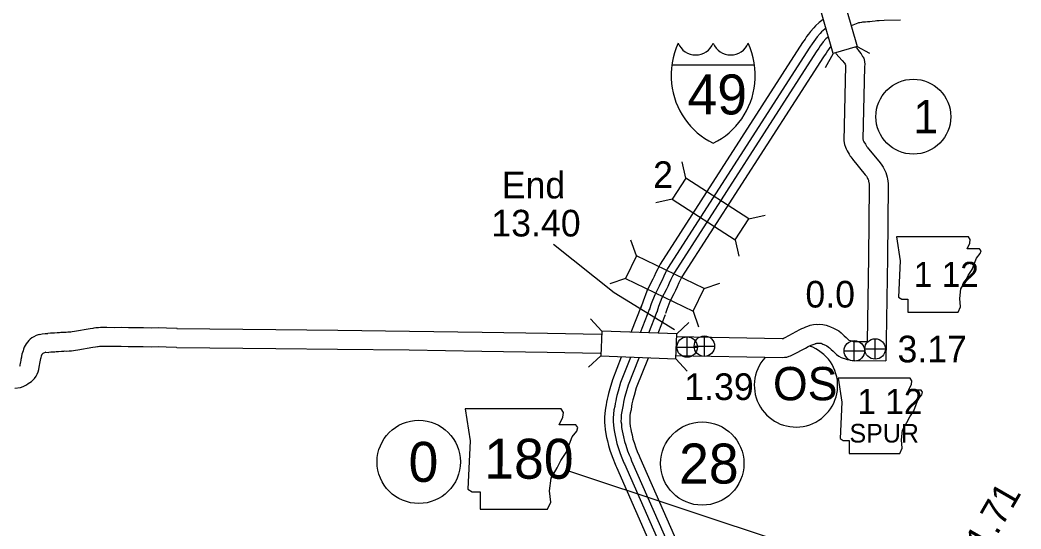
# Model space of a CAD drawing. Extents: x -939622 to -934245, y 1383184 to 1385301.
# Drawn here: x -936375.77 to -936328.22, y 1384954.58 to 1384978.78 of the extents above; entities that cross this region are included whole.
import ezdxf

# ---------------------------------------------------------------- set-up
doc = ezdxf.new("R2010")
doc.units = 0
for name, color, linetype in [('10', 7, 'Continuous'), ('19', 7, 'Continuous'), ('20', 7, 'Continuous'), ('21', 7, 'Continuous'), ('22', 7, 'Continuous'), ('23', 7, 'Continuous'), ('25', 7, 'Continuous'), ('26', 7, 'Continuous'), ('27', 7, 'Continuous')]:
    doc.layers.add(name, color=color, linetype=linetype)

msp = doc.modelspace()

# ---------------------------------------------------------------- linework, layer by layer
at = {"layer": '10'}
for points in [[(-936336.07, 1384977.478), (-936336.03, 1384977.434), (-936335.906, 1384977.282), (-936335.82, 1384977.17), (-936335.746, 1384977.033), (-936335.739, 1384977.02), (-936335.697, 1384976.953), (-936335.653, 1384976.803), (-936335.644, 1384976.662), (-936335.656, 1384976.563), (-936335.657, 1384976.552), (-936335.731, 1384973.105), (-936335.725, 1384973.072), (-936335.72, 1384973.054), (-936335.699, 1384973.01), (-936335.686, 1384972.977), (-936335.617, 1384972.876), (-936335.54, 1384972.746)], [(-936337.024, 1384977.185), (-936336.711, 1384976.845), (-936336.611, 1384976.723), (-936336.578, 1384976.679), (-936336.554, 1384976.634), (-936336.557, 1384976.596), (-936336.632, 1384973.033), (-936336.602, 1384972.863), (-936336.564, 1384972.737), (-936336.524, 1384972.649), (-936336.483, 1384972.55), (-936336.429, 1384972.47), (-936336.386, 1384972.396), (-936336.339, 1384972.31), (-936336.306, 1384972.273), (-936336.266, 1384972.207), (-936336.209, 1384972.144)], [(-936335.526, 1384972.73), (-936334.92, 1384971.982), (-936334.833, 1384971.874), (-936334.773, 1384971.778), (-936334.722, 1384971.686), (-936334.69, 1384971.614), (-936334.648, 1384971.52), (-936334.612, 1384971.414), (-936334.585, 1384971.31), (-936334.567, 1384971.206), (-936334.552, 1384971.133), (-936334.539, 1384970.99), (-936334.534, 1384970.89), (-936334.565, 1384967.491), (-936334.651, 1384962.577)], [(-936336.225, 1384972.163), (-936335.621, 1384971.417), (-936335.569, 1384971.352), (-936335.55, 1384971.322), (-936335.528, 1384971.283), (-936335.512, 1384971.247), (-936335.487, 1384971.192), (-936335.474, 1384971.154), (-936335.465, 1384971.12), (-936335.452, 1384971.037), (-936335.443, 1384970.997), (-936335.437, 1384970.93), (-936335.434, 1384970.874), (-936335.465, 1384967.503), (-936335.535, 1384963.488)], [(-936368.307, 1384964.112), (-936368.812, 1384964.129), (-936369.206, 1384964.134), (-936369.534, 1384964.129), (-936369.904, 1384964.14), (-936370.259, 1384964.141), (-936370.618, 1384964.14), (-936370.959, 1384964.151), (-936371.306, 1384964.149), (-936371.651, 1384964.16), (-936371.844, 1384964.159), (-936371.943, 1384964.152), (-936372.049, 1384964.149), (-936372.169, 1384964.14), (-936372.262, 1384964.123), (-936372.322, 1384964.111), (-936372.439, 1384964.099), (-936373.185, 1384963.97), (-936373.303, 1384963.947), (-936373.364, 1384963.935), (-936373.378, 1384963.934), (-936373.453, 1384963.933), (-936373.471, 1384963.93), (-936373.507, 1384963.931), (-936373.587, 1384963.923), (-936373.643, 1384963.927), (-936373.754, 1384963.923), (-936373.842, 1384963.918), (-936373.902, 1384963.909), (-936374.012, 1384963.903), (-936374.128, 1384963.893), (-936374.203, 1384963.887), (-936374.247, 1384963.882), (-936374.331, 1384963.882), (-936374.451, 1384963.875)], [(-936368.318, 1384964.112), (-936363.619, 1384964.061), (-936360.681, 1384964.028), (-936357.272, 1384963.988), (-936353.815, 1384963.939), (-936350.716, 1384963.886), (-936348.171, 1384963.834)], [(-936344.611, 1384963.724), (-936339.574, 1384963.634), (-936339.523, 1384963.638), (-936339.516, 1384963.64), (-936339.476, 1384963.664), (-936339.433, 1384963.682), (-936338.902, 1384963.964), (-936338.735, 1384964.065), (-936338.631, 1384964.106), (-936338.534, 1384964.144), (-936338.442, 1384964.183), (-936338.349, 1384964.219), (-936338.235, 1384964.268), (-936338.083, 1384964.294), (-936337.959, 1384964.309), (-936337.867, 1384964.306), (-936337.795, 1384964.309), (-936337.635, 1384964.305), (-936337.473, 1384964.272), (-936337.355, 1384964.228), (-936337.266, 1384964.191), (-936337.123, 1384964.124), (-936337.036, 1384964.082), (-936336.885, 1384963.999), (-936336.766, 1384963.907), (-936336.687, 1384963.829), (-936336.618, 1384963.763), (-936336.528, 1384963.674), (-936336.465, 1384963.614), (-936336.423, 1384963.574), (-936336.405, 1384963.562), (-936336.331, 1384963.541), (-936336.288, 1384963.526), (-936336.262, 1384963.518), (-936336.223, 1384963.505), (-936336.207, 1384963.501), (-936336.197, 1384963.499), (-936336.092, 1384963.495), (-936335.535, 1384963.488)], [(-936374.855, 1384963.823), (-936374.912, 1384963.801), (-936374.999, 1384963.773), (-936375.115, 1384963.717), (-936375.205, 1384963.662), (-936375.289, 1384963.603), (-936375.355, 1384963.537), (-936375.419, 1384963.464), (-936375.479, 1384963.384), (-936375.532, 1384963.299), (-936375.573, 1384963.224), (-936375.604, 1384963.131), (-936375.623, 1384963.033)], [(-936374.855, 1384963.823), (-936374.723, 1384963.854), (-936374.586, 1384963.866), (-936374.451, 1384963.875)], [(-936375.781, 1384962.317), (-936375.769, 1384962.349), (-936375.76, 1384962.377), (-936375.748, 1384962.44), (-936375.731, 1384962.529), (-936375.719, 1384962.581), (-936375.714, 1384962.656), (-936375.689, 1384962.769), (-936375.667, 1384962.9), (-936375.636, 1384962.992), (-936375.622, 1384963.04), (-936375.621, 1384963.045)], [(-936374.543, 1384962.978), (-936374.618, 1384962.951), (-936374.663, 1384962.936), (-936374.684, 1384962.926), (-936374.705, 1384962.913), (-936374.72, 1384962.896), (-936374.737, 1384962.873), (-936374.737, 1384962.873), (-936374.739, 1384962.861)], [(-936374.543, 1384962.978), (-936374.397, 1384962.976)], [(-936368.338, 1384963.212), (-936368.833, 1384963.229), (-936369.205, 1384963.234), (-936369.541, 1384963.229), (-936369.919, 1384963.24), (-936370.259, 1384963.241), (-936370.63, 1384963.24), (-936370.971, 1384963.251), (-936371.319, 1384963.249), (-936371.663, 1384963.26), (-936371.811, 1384963.259), (-936371.897, 1384963.253), (-936372.001, 1384963.25), (-936372.054, 1384963.246), (-936372.093, 1384963.239), (-936372.189, 1384963.22), (-936372.316, 1384963.207), (-936373.024, 1384963.084), (-936373.133, 1384963.064), (-936373.228, 1384963.045), (-936373.327, 1384963.034), (-936373.439, 1384963.034), (-936373.574, 1384963.019), (-936373.661, 1384963.026), (-936373.712, 1384963.024), (-936373.75, 1384963.022), (-936373.809, 1384963.013), (-936373.95, 1384963.005), (-936374.05, 1384962.997), (-936374.119, 1384962.991), (-936374.2, 1384962.982), (-936374.302, 1384962.982), (-936374.397, 1384962.976)], [(-936368.328, 1384963.212), (-936363.629, 1384963.161), (-936360.691, 1384963.128), (-936357.283, 1384963.088), (-936353.829, 1384963.039), (-936350.733, 1384962.986), (-936348.208, 1384962.934)], [(-936344.657, 1384962.825), (-936339.545, 1384962.733), (-936339.462, 1384962.74), (-936339.344, 1384962.741), (-936339.231, 1384962.787), (-936339.179, 1384962.805), (-936339.111, 1384962.835), (-936339.074, 1384962.857), (-936339.046, 1384962.869), (-936338.459, 1384963.18), (-936338.334, 1384963.255), (-936338.301, 1384963.269), (-936338.194, 1384963.31), (-936338.101, 1384963.35), (-936338.009, 1384963.386), (-936337.98, 1384963.398), (-936337.952, 1384963.403), (-936337.92, 1384963.407), (-936337.862, 1384963.405), (-936337.785, 1384963.408), (-936337.735, 1384963.407), (-936337.723, 1384963.405), (-936337.686, 1384963.391), (-936337.63, 1384963.368), (-936337.508, 1384963.31), (-936337.446, 1384963.281), (-936337.381, 1384963.245), (-936337.361, 1384963.23), (-936337.314, 1384963.183), (-936337.245, 1384963.117), (-936337.154, 1384963.027), (-936337.084, 1384962.961), (-936336.988, 1384962.87), (-936336.874, 1384962.793), (-936336.765, 1384962.733), (-936336.673, 1384962.703), (-936336.605, 1384962.683), (-936336.565, 1384962.669), (-936336.53, 1384962.659), (-936336.48, 1384962.642), (-936336.43, 1384962.629), (-936336.32, 1384962.602), (-936336.113, 1384962.595), (-936334.651, 1384962.577)], [(-936376.016, 1384961.267), (-936375.748, 1384961.302), (-936375.631, 1384961.358), (-936375.564, 1384961.388), (-936375.498, 1384961.417), (-936375.397, 1384961.477), (-936375.333, 1384961.52), (-936375.3, 1384961.545), (-936375.234, 1384961.584), (-936375.141, 1384961.678), (-936375.085, 1384961.74), (-936375.011, 1384961.847), (-936374.959, 1384961.946), (-936374.918, 1384962.052), (-936374.886, 1384962.156), (-936374.863, 1384962.274), (-936374.85, 1384962.346), (-936374.827, 1384962.445), (-936374.821, 1384962.526), (-936374.805, 1384962.598), (-936374.792, 1384962.679), (-936374.776, 1384962.725), (-936374.754, 1384962.802), (-936374.751, 1384962.813)], [(-936374.751, 1384962.813), (-936374.739, 1384962.861)]]:
    msp.add_lwpolyline(points, dxfattribs=at)
at = {"layer": '19'}
for points in [[(-936337.616, 1384978.802), (-936337.804, 1384978.655), (-936337.979, 1384978.504), (-936338.072, 1384978.406), (-936338.224, 1384978.235), (-936338.32, 1384978.109), (-936338.413, 1384977.988), (-936338.484, 1384977.869), (-936338.6, 1384977.711), (-936345.369, 1384967.172), (-936345.482, 1384966.954), (-936345.574, 1384966.77), (-936345.653, 1384966.576), (-936345.712, 1384966.453), (-936345.787, 1384966.306), (-936346, 1384965.88), (-936346.179, 1384965.414), (-936346.269, 1384965.137), (-936346.28, 1384965.085)], [(-936333.943, 1384978.775), (-936334.72, 1384978.753), (-936334.954, 1384978.74), (-936335.066, 1384978.732), (-936335.151, 1384978.718), (-936335.301, 1384978.703), (-936335.411, 1384978.696), (-936335.518, 1384978.687), (-936335.605, 1384978.68), (-936335.692, 1384978.676), (-936335.747, 1384978.672), (-936335.802, 1384978.663), (-936335.881, 1384978.641), (-936335.935, 1384978.635), (-936335.976, 1384978.624)], [(-936337.482, 1384978.383), (-936337.543, 1384978.336), (-936337.694, 1384978.206), (-936337.768, 1384978.127), (-936337.905, 1384977.972), (-936337.993, 1384977.858), (-936338.071, 1384977.756), (-936338.14, 1384977.641), (-936338.26, 1384977.477), (-936345.012, 1384966.965), (-936345.114, 1384966.767), (-936345.198, 1384966.6), (-936345.275, 1384966.409), (-936345.343, 1384966.269), (-936345.419, 1384966.12), (-936345.622, 1384965.714), (-936345.79, 1384965.277), (-936345.871, 1384965.027), (-936345.878, 1384964.993)], [(-936335.976, 1384978.624), (-936336.284, 1384978.504)], [(-936337.37, 1384977.99), (-936337.434, 1384977.934), (-936337.491, 1384977.874), (-936337.616, 1384977.733), (-936337.695, 1384977.63), (-936337.76, 1384977.546), (-936337.827, 1384977.433), (-936337.951, 1384977.265), (-936344.686, 1384966.777), (-936344.78, 1384966.597), (-936344.856, 1384966.445), (-936344.932, 1384966.257), (-936345.007, 1384966.102), (-936345.085, 1384965.95), (-936345.279, 1384965.562), (-936345.436, 1384965.152), (-936345.509, 1384964.927), (-936345.513, 1384964.909)], [(-936337.246, 1384977.529), (-936337.298, 1384977.471), (-936337.368, 1384977.379), (-936337.418, 1384977.314), (-936337.483, 1384977.204), (-936337.611, 1384977.031), (-936344.329, 1384966.571), (-936344.412, 1384966.41), (-936344.48, 1384966.275), (-936344.555, 1384966.09), (-936344.638, 1384965.918), (-936344.717, 1384965.764), (-936344.901, 1384965.396), (-936345.047, 1384965.015), (-936345.111, 1384964.817), (-936345.111, 1384964.815)], [(-936346.248, 1384965.197), (-936346.753, 1384963.915)], [(-936345.864, 1384965.045), (-936346.316, 1384963.897)], [(-936345.515, 1384964.908), (-936345.918, 1384963.884)], [(-936345.131, 1384964.757), (-936345.479, 1384963.874)], [(-936347.215, 1384962.74), (-936347.635, 1384961.672), (-936347.76, 1384961.247), (-936347.819, 1384961.023), (-936347.857, 1384960.872), (-936347.883, 1384960.749), (-936347.906, 1384960.606), (-936347.926, 1384960.48), (-936347.965, 1384960.321), (-936347.999, 1384960.083), (-936348.009, 1384959.875), (-936348.015, 1384959.645), (-936347.992, 1384959.492), (-936347.979, 1384959.307), (-936347.944, 1384959.102), (-936347.908, 1384958.927), (-936347.867, 1384958.777), (-936347.816, 1384958.54), (-936347.749, 1384958.331), (-936347.65, 1384958.018), (-936347.469, 1384957.574)], [(-936346.775, 1384962.732), (-936347.245, 1384961.538), (-936347.363, 1384961.137), (-936347.419, 1384960.92), (-936347.455, 1384960.778), (-936347.478, 1384960.674), (-936347.499, 1384960.542), (-936347.521, 1384960.399), (-936347.559, 1384960.242), (-936347.588, 1384960.044), (-936347.596, 1384959.86), (-936347.602, 1384959.67), (-936347.582, 1384959.538), (-936347.569, 1384959.356), (-936347.539, 1384959.179), (-936347.506, 1384959.023), (-936347.467, 1384958.875), (-936347.417, 1384958.647), (-936347.356, 1384958.456), (-936347.262, 1384958.16), (-936347.181, 1384957.965), (-936347.088, 1384957.73)], [(-936346.382, 1384962.707), (-936346.89, 1384961.416), (-936347.001, 1384961.037), (-936347.056, 1384960.827), (-936347.09, 1384960.692), (-936347.109, 1384960.605), (-936347.128, 1384960.484), (-936347.153, 1384960.326), (-936347.191, 1384960.171), (-936347.214, 1384960.009), (-936347.222, 1384959.845), (-936347.226, 1384959.693), (-936347.209, 1384959.579), (-936347.196, 1384959.401), (-936347.17, 1384959.248), (-936347.142, 1384959.11), (-936347.102, 1384958.964), (-936347.054, 1384958.743), (-936346.999, 1384958.569), (-936346.91, 1384958.289), (-936346.834, 1384958.107), (-936346.781, 1384957.974)], [(-936345.941, 1384962.701), (-936346.499, 1384961.283), (-936346.604, 1384960.926), (-936346.657, 1384960.723), (-936346.688, 1384960.599), (-936346.703, 1384960.529), (-936346.721, 1384960.419), (-936346.748, 1384960.246), (-936346.785, 1384960.092), (-936346.803, 1384959.97), (-936346.809, 1384959.83), (-936346.813, 1384959.718), (-936346.799, 1384959.625), (-936346.786, 1384959.45), (-936346.765, 1384959.325), (-936346.74, 1384959.207), (-936346.701, 1384959.062), (-936346.655, 1384958.85), (-936346.606, 1384958.694), (-936346.522, 1384958.432), (-936346.452, 1384958.263), (-936346.368, 1384958.053)], [(-936347.088, 1384957.73), (-936347.065, 1384957.673), (-936343.733, 1384950.096), (-936343.233, 1384948.977), (-936342.758, 1384947.86), (-936342.573, 1384947.412), (-936342.485, 1384947.217), (-936342.425, 1384947.071), (-936342.368, 1384946.894), (-936342.316, 1384946.757), (-936342.27, 1384946.624), (-936342.216, 1384946.438), (-936342.151, 1384946.228), (-936342.118, 1384946.053), (-936342.059, 1384945.847), (-936342.014, 1384945.642), (-936341.968, 1384945.439), (-936341.929, 1384945.276), (-936341.454, 1384942.565), (-936341.414, 1384942.38)], [(-936346.781, 1384957.974), (-936346.719, 1384957.818), (-936343.39, 1384950.247), (-936342.89, 1384949.127), (-936342.413, 1384948.005), (-936342.229, 1384947.561), (-936342.14, 1384947.366), (-936342.073, 1384947.2), (-936342.014, 1384947.018), (-936341.963, 1384946.885), (-936341.912, 1384946.737), (-936341.856, 1384946.545), (-936341.787, 1384946.318), (-936341.753, 1384946.14), (-936341.695, 1384945.938), (-936341.648, 1384945.724), (-936341.603, 1384945.524), (-936341.562, 1384945.352), (-936341.086, 1384942.637), (-936341.051, 1384942.473)], [(-936346.368, 1384958.053), (-936346.338, 1384957.977), (-936343.013, 1384950.415), (-936342.511, 1384949.292), (-936342.032, 1384948.164), (-936341.85, 1384947.724), (-936341.761, 1384947.529), (-936341.685, 1384947.342), (-936341.625, 1384947.155), (-936341.576, 1384947.027), (-936341.519, 1384946.862), (-936341.461, 1384946.663), (-936341.386, 1384946.418), (-936341.351, 1384946.235), (-936341.295, 1384946.039), (-936341.246, 1384945.814), (-936341.201, 1384945.618), (-936341.158, 1384945.435), (-936340.681, 1384942.716), (-936340.672, 1384942.676)], [(-936347.469, 1384957.574), (-936347.446, 1384957.514), (-936344.11, 1384949.928), (-936343.612, 1384948.812), (-936343.139, 1384947.7), (-936342.951, 1384947.248), (-936342.864, 1384947.054), (-936342.813, 1384946.93), (-936342.757, 1384946.757), (-936342.703, 1384946.616), (-936342.663, 1384946.499), (-936342.611, 1384946.32), (-936342.552, 1384946.128), (-936342.52, 1384945.957), (-936342.459, 1384945.746), (-936342.417, 1384945.551), (-936342.37, 1384945.346), (-936342.333, 1384945.193), (-936341.859, 1384942.486), (-936341.825, 1384942.327)]]:
    msp.add_lwpolyline(points, dxfattribs=at)
at = {"layer": '20'}
for p, q in [((-936336.001, 1384977.518), (-936335.428, 1384977.201)), ((-936337.143, 1384977.19), (-936337.527, 1384976.497)), ((-936344.151, 1384971.256), (-936344.32, 1384972.029)), ((-936344.793, 1384970.256), (-936345.567, 1384970.087)), ((-936341.152, 1384969.33), (-936340.378, 1384969.498)), ((-936346.492, 1384967.557), (-936346.753, 1384968.305)), ((-936341.794, 1384968.33), (-936341.626, 1384967.556)), ((-936347.008, 1384966.487), (-936347.756, 1384966.226)), ((-936347.556, 1384965.814), (-936344.689, 1384964.069)), ((-936343.282, 1384966.008), (-936342.534, 1384966.269)), ((-936343.798, 1384964.938), (-936343.537, 1384964.19)), ((-936348.142, 1384963.99), (-936348.68, 1384964.571)), ((-936344.58, 1384963.857), (-936344, 1384964.396)), ((-936348.186, 1384962.803), (-936348.766, 1384962.264)), ((-936344.624, 1384962.67), (-936344.086, 1384962.089))]:
    msp.add_line(p, q, dxfattribs=at)
for points in [[(-936338.127, 1384980.616), (-936336.985, 1384980.944), (-936336.001, 1384977.518), (-936337.143, 1384977.19)], [(-936341.152, 1384969.33), (-936344.151, 1384971.256), (-936344.793, 1384970.256), (-936341.794, 1384968.33)], [(-936343.282, 1384966.008), (-936346.492, 1384967.557), (-936347.008, 1384966.487), (-936343.798, 1384964.938)], [(-936344.58, 1384963.857), (-936348.142, 1384963.99), (-936348.186, 1384962.803), (-936344.624, 1384962.67)]]:
    msp.add_lwpolyline(points, close=True, dxfattribs=at)
at = {"layer": '21'}
msp.add_line((-936349.812, 1384957.368), (-936339.097, 1384953.808), dxfattribs=at)
for points in [[(-936334.138, 1384968.47), (-936333.967, 1384967.328), (-936334.043, 1384965.596), (-936333.891, 1384965.501), (-936333.605, 1384965.501), (-936333.605, 1384964.892), (-936331.207, 1384964.892), (-936331.093, 1384965.139), (-936331.131, 1384965.539), (-936331.074, 1384965.996), (-936330.865, 1384966.357), (-936330.731, 1384966.624), (-936330.541, 1384966.909), (-936330.427, 1384967.214), (-936330.332, 1384967.461), (-936330.16, 1384967.671), (-936330.122, 1384967.804), (-936330.198, 1384967.899), (-936330.788, 1384967.899), (-936330.655, 1384968.166), (-936330.636, 1384968.337), (-936330.715, 1384968.468)], [(-936336.912, 1384961.753), (-936336.741, 1384960.611), (-936336.817, 1384958.879), (-936336.665, 1384958.784), (-936336.379, 1384958.784), (-936336.379, 1384958.175), (-936333.981, 1384958.175), (-936333.867, 1384958.423), (-936333.905, 1384958.822), (-936333.848, 1384959.279), (-936333.639, 1384959.641), (-936333.505, 1384959.907), (-936333.315, 1384960.193), (-936333.201, 1384960.497), (-936333.106, 1384960.745), (-936332.934, 1384960.954), (-936332.896, 1384961.087), (-936332.972, 1384961.182), (-936333.563, 1384961.182), (-936333.429, 1384961.449), (-936333.41, 1384961.62), (-936333.489, 1384961.752)], [(-936354.626, 1384960.297), (-936354.397, 1384958.775), (-936354.499, 1384956.465), (-936354.296, 1384956.339), (-936353.915, 1384956.339), (-936353.915, 1384955.526), (-936350.718, 1384955.526), (-936350.565, 1384955.856), (-936350.616, 1384956.389), (-936350.54, 1384956.998), (-936350.261, 1384957.48), (-936350.083, 1384957.836), (-936349.83, 1384958.216), (-936349.677, 1384958.622), (-936349.55, 1384958.952), (-936349.322, 1384959.231), (-936349.271, 1384959.409), (-936349.373, 1384959.536), (-936350.159, 1384959.536), (-936349.982, 1384959.891), (-936349.956, 1384960.12), (-936350.062, 1384960.295)]]:
    msp.add_lwpolyline(points, close=True, dxfattribs=at)
at = {"layer": '23'}
msp.add_line((-936344.811, 1384976.64), (-936340.878, 1384976.64), dxfattribs=at)
for centre, radius, start, end in [((-936341.157, 1384976.128), 3.69, 155.2204, 185.7928), ((-936343.674, 1384978.013), 0.899, 202.1459, 337.3414), ((-936342.015, 1384978.013), 0.899, 202.6586, 337.8541), ((-936344.533, 1384976.128), 3.69, 354.2072, 24.7796), ((-936341.224, 1384976.159), 3.626, 186.3923, 243.4571), ((-936344.465, 1384976.159), 3.626, 296.5429, 353.6077)]:
    msp.add_arc(centre, radius, start, end, dxfattribs=at)
at = {"layer": '25'}
for p, q in [((-936350.424, 1384968.121), (-936347.556, 1384965.814)), ((-936347.556, 1384965.814), (-936344.689, 1384964.069))]:
    msp.add_line(p, q, dxfattribs=at)
at = {"layer": '26'}
for p, q in [((-936344.083, 1384962.739), (-936344.083, 1384963.714)), ((-936343.264, 1384962.783), (-936343.264, 1384963.758)), ((-936336.141, 1384962.557), (-936336.141, 1384963.532)), ((-936335.155, 1384962.649), (-936335.155, 1384963.624)), ((-936344.571, 1384963.227), (-936343.596, 1384963.227)), ((-936343.752, 1384963.271), (-936342.777, 1384963.271)), ((-936336.628, 1384963.045), (-936335.653, 1384963.045)), ((-936335.642, 1384963.137), (-936334.667, 1384963.137))]:
    msp.add_line(p, q, dxfattribs=at)
for centre in [(-936344.083, 1384963.227), (-936343.264, 1384963.271), (-936336.141, 1384963.045), (-936335.155, 1384963.137)]:
    msp.add_circle(centre, 0.487, dxfattribs=at)
at = {"layer": '27'}
for centre, radius in [((-936333.338, 1384974.179), 1.782), ((-936356.832, 1384957.769), 1.98), ((-936343.366, 1384957.69), 1.98)]:
    msp.add_circle(centre, radius, dxfattribs=at)
msp.add_arc((-936338.912, 1384961.404), 1.98, 137.938, 71.1287, dxfattribs=at)

# ---------------------------------------------------------------- texts
at = {"layer": '20'}
msp.add_text('2', height=1.267, dxfattribs=at).set_placement((-936345.698, 1384970.788))
at = {"layer": '21'}
for s, height, p in [('49', 1.9008, (-936344.066, 1384974.286)), ('1 12', 1.188, (-936333.318, 1384966.089)), ('1 12', 1.188, (-936335.998, 1384960.049))]:
    msp.add_text(s, height=height, dxfattribs=at).set_placement(p)
msp.add_text('180', height=1.9008, rotation=359.9, dxfattribs=at).set_placement((-936353.719, 1384956.972))
at = {"layer": '22'}
msp.add_text('SPUR', height=0.887, dxfattribs=at).set_placement((-936336.37, 1384958.688))
at = {"layer": '25'}
for s, p in [('End', (-936352.89, 1384970.292)), ('13.40', (-936353.382, 1384968.484)), ('0.0', (-936338.465, 1384965.107)), ('3.17', (-936334.089, 1384962.5)), ('1.39', (-936344.218, 1384960.71))]:
    msp.add_text(s, height=1.2672, dxfattribs=at).set_placement(p)
msp.add_text('1.71', height=1.2672, rotation=60, dxfattribs=at).set_placement((-936329.832, 1384953.429))
at = {"layer": '27'}
for s, p in [('1', (-936333.338, 1384973.387)), ('OS', (-936340.005, 1384960.697))]:
    msp.add_text(s, height=1.584, dxfattribs=at).set_placement(p)
for s, height, p in [('0', 1.901, (-936357.318, 1384956.82)), ('28', 1.9008, (-936344.466, 1384956.741))]:
    msp.add_text(s, height=height, rotation=359.9, dxfattribs=at).set_placement(p)

doc.saveas('drawing.dxf')
